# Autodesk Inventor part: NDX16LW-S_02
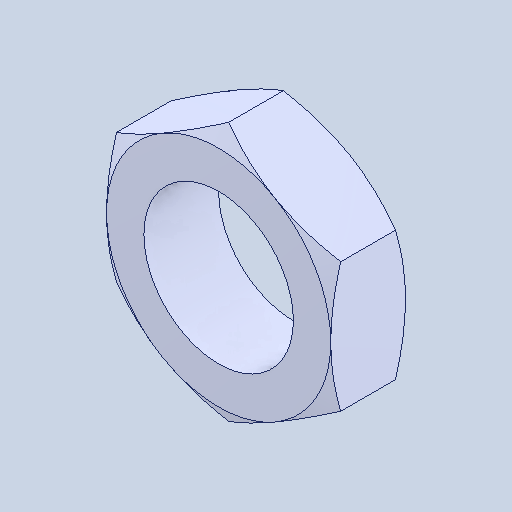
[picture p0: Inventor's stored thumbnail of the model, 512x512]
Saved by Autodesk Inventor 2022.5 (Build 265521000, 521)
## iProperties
Created: 2024-05
Part Number: NDX16LW-S_02
Material: 一般
Document SubType Name: Modeling
Designer: ImaoCorp
Density: 1 g/cm^3
Appearance: 既定
Author: ImaoCorp
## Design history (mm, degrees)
feature "NDX16LW-S_02"
node "ソリッド1"
